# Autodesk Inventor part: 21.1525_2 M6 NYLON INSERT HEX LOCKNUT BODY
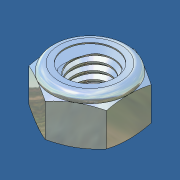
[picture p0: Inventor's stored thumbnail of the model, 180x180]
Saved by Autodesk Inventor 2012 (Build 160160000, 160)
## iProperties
Created: 2012-02
Part Number: 21.1525_2 M6 NYLON INSERT HEX LOCKNUT BODY
Material: Steel
Document SubType Name: Modeling
Designer: Administrator
Stock Number: M6 Nylon-Insert Hex Locknuts
Mass: 2.49269 g
Surface Area: 5.32984 cm^2
Volume: 0.31754 cm^3
Density: 7.85 g/cm^3
Author: Administrator
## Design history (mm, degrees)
feature "Base1"
body "Solid1"
